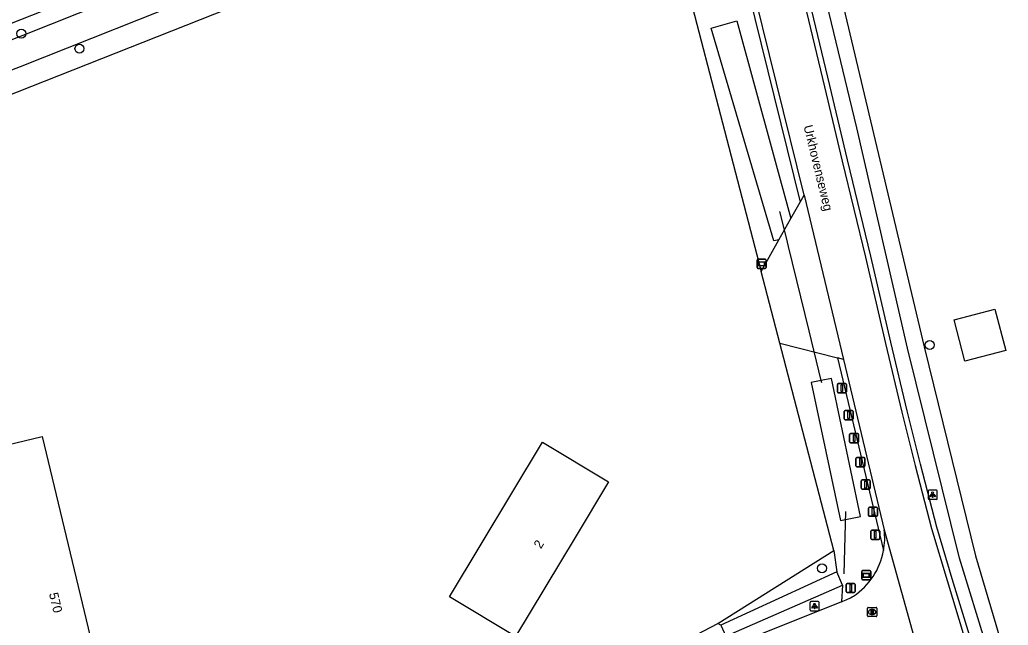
# Model space of a CAD drawing. Extents: x 164494 to 166241, y 382475 to 384494.
# Drawn here: x 164719.3 to 164827, y 383502.5 to 383568.4 of the extents above; entities that cross this region are included whole.
import ezdxf

# ---------------------------------------------------------------- set-up
doc = ezdxf.new("R2010")
doc.units = 0
for name, color, linetype in [('IMGEO_Afsluitpaal', 7, 'Continuous'), ('IMGEO_Berm_halfverhard', 7, 'Continuous'), ('IMGEO_Boom', 7, 'Continuous'), ('IMGEO_Duiker', 7, 'Continuous'), ('IMGEO_Fietspad_open', 7, 'Continuous'), ('IMGEO_Groenvoorziening', 7, 'Continuous'), ('IMGEO_Lichtpunt', 7, 'Continuous'), ('IMGEO_Openbare_ruimte_label', 7, 'Continuous'), ('IMGEO_Pand', 7, 'Continuous'), ('IMGEO_Pand_nummerreeks', 7, 'Continuous'), ('IMGEO_Rijbaan_lokaal_gesloten', 7, 'Continuous'), ('IMGEO_Rijbaan_lokaal_open', 7, 'Continuous'), ('IMGEO_Rioolput', 7, 'Continuous'), ('IMGEO_Straatnaambord', 7, 'Continuous'), ('IMGEO_Verklikker', 7, 'Continuous'), ('IMGEO_Voetpad_open', 7, 'Continuous'), ('IMGEO_Waterloop', 7, 'Continuous')]:
    doc.layers.add(name, color=color, linetype=linetype)

msp = doc.modelspace()

# ---------------------------------------------------------------- linework, layer by layer
at = {"layer": 'IMGEO_Afsluitpaal'}
for p, q in [((164808.38, 383527.91), (164808.38, 383528.71)), ((164808.38, 383528.71), (164808.38, 383527.91)), ((164808.48, 383528.81), (164809.27, 383528.81)), ((164809.27, 383528.81), (164808.48, 383528.81)), ((164809.37, 383528.71), (164809.37, 383527.91)), ((164809.37, 383527.91), (164809.37, 383528.71)), ((164809.27, 383527.81), (164808.48, 383527.81)), ((164808.48, 383527.81), (164809.27, 383527.81)), ((164809.22, 383525.88), (164810.01, 383525.88)), ((164810.01, 383525.88), (164809.22, 383525.88)), ((164809.12, 383524.98), (164809.12, 383525.78)), ((164809.12, 383525.78), (164809.12, 383524.98)), ((164810.01, 383524.88), (164809.22, 383524.88)), ((164809.22, 383524.88), (164810.01, 383524.88)), ((164810.11, 383525.78), (164810.11, 383524.98)), ((164810.11, 383524.98), (164810.11, 383525.78)), ((164809.71, 383522.47), (164809.71, 383523.27)), ((164809.71, 383523.27), (164809.71, 383522.47)), ((164809.81, 383523.37), (164810.6, 383523.37)), ((164810.6, 383523.37), (164809.81, 383523.37)), ((164810.7, 383523.27), (164810.7, 383522.47)), ((164810.7, 383522.47), (164810.7, 383523.27)), ((164810.6, 383522.37), (164809.81, 383522.37)), ((164809.81, 383522.37), (164810.6, 383522.37)), ((164810.4, 383519.86), (164810.4, 383520.66)), ((164810.4, 383520.66), (164810.4, 383519.86)), ((164810.5, 383520.76), (164811.29, 383520.76)), ((164811.29, 383520.76), (164810.5, 383520.76)), ((164811.39, 383520.66), (164811.39, 383519.86)), ((164811.39, 383519.86), (164811.39, 383520.66)), ((164811.29, 383519.76), (164810.5, 383519.76)), ((164810.5, 383519.76), (164811.29, 383519.76)), ((164810.97, 383517.42), (164810.97, 383518.22)), ((164810.97, 383518.22), (164810.97, 383517.42)), ((164811.07, 383518.32), (164811.86, 383518.32)), ((164811.86, 383518.32), (164811.07, 383518.32)), ((164811.86, 383517.32), (164811.07, 383517.32)), ((164811.07, 383517.32), (164811.86, 383517.32)), ((164811.96, 383518.22), (164811.96, 383517.42)), ((164811.96, 383517.42), (164811.96, 383518.22)), ((164811.77, 383514.46), (164811.77, 383515.26)), ((164811.77, 383515.26), (164811.77, 383514.46)), ((164811.87, 383515.36), (164812.66, 383515.36)), ((164812.66, 383515.36), (164811.87, 383515.36)), ((164812.76, 383515.26), (164812.76, 383514.46)), ((164812.76, 383514.46), (164812.76, 383515.26)), ((164812.66, 383514.36), (164811.87, 383514.36)), ((164811.87, 383514.36), (164812.66, 383514.36)), ((164812.02, 383511.95), (164812.02, 383512.75)), ((164812.02, 383512.75), (164812.02, 383511.95)), ((164812.12, 383512.85), (164812.91, 383512.85)), ((164812.91, 383512.85), (164812.12, 383512.85)), ((164813.01, 383512.75), (164813.01, 383511.95)), ((164813.01, 383511.95), (164813.01, 383512.75)), ((164812.91, 383511.85), (164812.12, 383511.85)), ((164812.12, 383511.85), (164812.91, 383511.85)), ((164809.34, 383506.16), (164809.34, 383506.95)), ((164809.34, 383506.95), (164809.34, 383506.16)), ((164809.44, 383507.05), (164810.23, 383507.05)), ((164810.23, 383507.05), (164809.44, 383507.05)), ((164810.33, 383506.95), (164810.33, 383506.16)), ((164810.33, 383506.16), (164810.33, 383506.95)), ((164810.23, 383506.06), (164809.44, 383506.06)), ((164809.44, 383506.06), (164810.23, 383506.06))]:
    msp.add_line(p, q, dxfattribs=at)
for points in [[(164808.8, 383528.69), (164808.95, 383528.69), (164808.95, 383527.94), (164808.8, 383527.94), (164808.8, 383528.69)], [(164809.54, 383525.76), (164809.69, 383525.76), (164809.69, 383525.01), (164809.54, 383525.01), (164809.54, 383525.76)], [(164810.13, 383523.25), (164810.28, 383523.25), (164810.28, 383522.5), (164810.13, 383522.5), (164810.13, 383523.25)], [(164810.82, 383520.64), (164810.97, 383520.64), (164810.97, 383519.89), (164810.82, 383519.89), (164810.82, 383520.64)], [(164811.39, 383518.19), (164811.54, 383518.19), (164811.54, 383517.44), (164811.39, 383517.44), (164811.39, 383518.19)], [(164812.19, 383515.24), (164812.34, 383515.24), (164812.34, 383514.49), (164812.19, 383514.49), (164812.19, 383515.24)], [(164812.44, 383512.73), (164812.59, 383512.73), (164812.59, 383511.98), (164812.44, 383511.98), (164812.44, 383512.73)], [(164809.76, 383506.93), (164809.91, 383506.93), (164809.91, 383506.18), (164809.76, 383506.18), (164809.76, 383506.93)]]:
    msp.add_lwpolyline(points, dxfattribs=at)
for centre, start, end in [((164808.48, 383528.71), 90, 180), ((164808.48, 383528.71), 90, 180), ((164809.27, 383528.71), 0, 90), ((164809.27, 383528.71), 360, 90), ((164808.48, 383527.91), 180, 270), ((164808.48, 383527.91), 180, 270), ((164809.27, 383527.91), 270, 0), ((164809.27, 383527.91), 270, 0), ((164809.22, 383525.78), 90, 180), ((164809.22, 383525.78), 90, 180), ((164810.01, 383525.78), 0, 90), ((164810.01, 383525.78), 360, 90), ((164809.22, 383524.98), 180, 270), ((164809.22, 383524.98), 180, 270), ((164810.01, 383524.98), 270, 0), ((164810.01, 383524.98), 270, 0), ((164809.81, 383523.27), 90, 180), ((164809.81, 383523.27), 90, 180), ((164810.6, 383523.27), 0, 90), ((164810.6, 383523.27), 360, 90), ((164809.81, 383522.47), 180, 270), ((164809.81, 383522.47), 180, 270), ((164810.6, 383522.47), 270, 0), ((164810.6, 383522.47), 270, 0), ((164810.5, 383520.66), 90, 180), ((164810.5, 383520.66), 90, 180), ((164811.29, 383520.66), 0, 90), ((164811.29, 383520.66), 360, 90), ((164810.5, 383519.86), 180, 270), ((164810.5, 383519.86), 180, 270), ((164811.29, 383519.86), 270, 0), ((164811.29, 383519.86), 270, 0), ((164811.07, 383518.22), 90, 180), ((164811.07, 383518.22), 90, 180), ((164811.07, 383517.42), 180, 270), ((164811.07, 383517.42), 180, 270), ((164811.86, 383518.22), 0, 90), ((164811.86, 383518.22), 360, 90), ((164811.86, 383517.42), 270, 0), ((164811.86, 383517.42), 270, 0), ((164811.87, 383515.26), 90, 180), ((164811.87, 383515.26), 90, 180), ((164812.66, 383515.26), 0, 90), ((164812.66, 383515.26), 360, 90), ((164811.87, 383514.46), 180, 270), ((164811.87, 383514.46), 180, 270), ((164812.66, 383514.46), 270, 0), ((164812.66, 383514.46), 270, 0), ((164812.12, 383512.75), 90, 180), ((164812.12, 383512.75), 90, 180), ((164812.12, 383511.95), 180, 270), ((164812.12, 383511.95), 180, 270), ((164812.91, 383512.75), 0, 90), ((164812.91, 383512.75), 360, 90), ((164812.91, 383511.95), 270, 0), ((164812.91, 383511.95), 270, 0), ((164809.44, 383506.95), 90, 180), ((164809.44, 383506.95), 90, 180), ((164810.23, 383506.95), 0, 90), ((164810.23, 383506.95), 360, 90), ((164809.44, 383506.16), 180, 270), ((164809.44, 383506.16), 180, 270), ((164810.23, 383506.16), 270, 0), ((164810.23, 383506.16), 270, 0)]:
    msp.add_arc(centre, 0.1, start, end, dxfattribs=at)
at = {"layer": 'IMGEO_Berm_halfverhard'}
for points in [[(164824.21, 383497.04), (164822.78, 383501.42), (164820.9, 383507.55), (164819.23, 383513.17), (164817.43, 383520.04), (164815.99, 383525.83), (164814.22, 383533.33), (164812.04, 383542.71), (164809.5, 383553.19), (164807.57, 383561.29), (164803.45, 383578.4), (164801.35, 383586.99), (164800.92, 383586.88)], [(164795.71, 383585.96), (164795.13, 383585.81), (164804.32, 383548.59)], [(164808.4, 383531.62), (164813.41, 383510.63)]]:
    msp.add_lwpolyline(points, dxfattribs=at)
at = {"layer": 'IMGEO_Boom'}
for centre in [(164719.49, 383566.93), (164725.83, 383565.3), (164818.45, 383533.02), (164806.71, 383508.7)]:
    msp.add_circle(centre, 0.489, dxfattribs=at)
at = {"layer": 'IMGEO_Duiker'}
for points in [[(164806.69, 383528.89), (164806.63, 383529.16), (164805.3, 383534.57), (164803.06, 383543.73), (164802.83, 383544.68), (164802.13, 383547.55)], [(164809.12, 383508.11), (164809.32, 383514.9)]]:
    msp.add_lwpolyline(points, dxfattribs=at)
at = {"layer": 'IMGEO_Fietspad_open'}
for points in [[(164780.31, 383592.48), (164780.67, 383591.01), (164719.66, 383566.74), (164702.48, 383560.05), (164631.23, 383531.62)], [(164543.61, 383493.49), (164560.1, 383500), (164646.9, 383534.43), (164687.9, 383550.87), (164703.45, 383557.25), (164719.42, 383563.36), (164781.38, 383588), (164789.86, 383591.37)]]:
    msp.add_lwpolyline(points, dxfattribs=at)
at = {"layer": 'IMGEO_Groenvoorziening'}
for points in [[(164787.93, 383587.83), (164800.09, 383541.03)], [(164807.99, 383510.62), (164802.12, 383533.21)], [(164795.36, 383502.7), (164807.99, 383510.62)], [(164807.99, 383510.62), (164808.34, 383508.3)], [(164808.96, 383506.85), (164808.83, 383505.04)], [(164757.54, 383480.47), (164762.71, 383483.34), (164781.14, 383494.37), (164788.51, 383499.08), (164795.36, 383502.7)], [(164795.7, 383502.5), (164795.36, 383502.7)]]:
    msp.add_lwpolyline(points, dxfattribs=at)
at = {"layer": 'IMGEO_Lichtpunt'}
for p, q in [((164818.26, 383517.11), (164818.26, 383516.3)), ((164818.26, 383517.11), (164818.26, 383516.3)), ((164819.17, 383517.2), (164818.36, 383517.2)), ((164819.17, 383517.2), (164818.36, 383517.2)), ((164818.36, 383516.21), (164819.17, 383516.21)), ((164818.36, 383516.21), (164819.17, 383516.21)), ((164819.26, 383516.3), (164819.26, 383517.11)), ((164819.26, 383516.3), (164819.26, 383517.11)), ((164805.4, 383504.98), (164805.4, 383504.18)), ((164805.4, 383504.98), (164805.4, 383504.18)), ((164806.3, 383505.08), (164805.5, 383505.08)), ((164806.3, 383505.08), (164805.5, 383505.08)), ((164806.4, 383504.18), (164806.4, 383504.98)), ((164806.4, 383504.18), (164806.4, 383504.98)), ((164805.5, 383504.08), (164806.3, 383504.08)), ((164805.5, 383504.08), (164806.3, 383504.08))]:
    msp.add_line(p, q, dxfattribs=at)
for points in [[(164818.64, 383516.77), (164818.68, 383516.74), (164818.49, 383516.48), (164818.45, 383516.51), (164818.64, 383516.77)], [(164818.74, 383516.72), (164818.79, 383516.72), (164818.79, 383516.4), (164818.74, 383516.4), (164818.74, 383516.72)], [(164818.85, 383516.74), (164818.89, 383516.77), (164819.08, 383516.51), (164819.04, 383516.48), (164818.85, 383516.74)], [(164805.78, 383504.65), (164805.81, 383504.62), (164805.63, 383504.36), (164805.59, 383504.38), (164805.78, 383504.65)], [(164805.88, 383504.6), (164805.92, 383504.6), (164805.92, 383504.28), (164805.88, 383504.28), (164805.88, 383504.6)], [(164805.99, 383504.62), (164806.03, 383504.65), (164806.21, 383504.38), (164806.17, 383504.36), (164805.99, 383504.62)]]:
    msp.add_lwpolyline(points, dxfattribs=at)
for centre in [(164818.76, 383516.91), (164805.9, 383504.78)]:
    msp.add_circle(centre, 0.0994, dxfattribs=at)
for centre, start, end in [((164818.36, 383517.11), 90, 180), ((164818.36, 383517.11), 90, 180), ((164818.36, 383516.3), 180, 270), ((164818.36, 383516.3), 180, 270), ((164819.17, 383517.11), 0, 90), ((164819.17, 383517.11), 0, 90), ((164819.17, 383516.3), 270, 0), ((164819.17, 383516.3), 270, 360), ((164805.5, 383504.98), 90, 180), ((164805.5, 383504.98), 90, 180), ((164806.3, 383504.98), 0, 90), ((164806.3, 383504.98), 0, 90), ((164805.5, 383504.18), 180, 270), ((164805.5, 383504.18), 180, 270), ((164806.3, 383504.18), 270, 0), ((164806.3, 383504.18), 270, 360)]:
    msp.add_arc(centre, 0.0946, start, end, dxfattribs=at)
at = {"layer": 'IMGEO_Pand'}
for points in [[(164826.72, 383532.41), (164822.26, 383531.25), (164821.1, 383535.75), (164825.55, 383536.91), (164826.72, 383532.41)], [(164730.27, 383487.65), (164656.03, 383469.75), (164647.47, 383505.18), (164721.76, 383523.07), (164730.27, 383487.65)], [(164776.26, 383522.42), (164783.45, 383518.11), (164779.82, 383512.07), (164773.34, 383501.28), (164766.15, 383505.6), (164776.26, 383522.42)]]:
    msp.add_lwpolyline(points, dxfattribs=at)
at = {"layer": 'IMGEO_Rijbaan_lokaal_gesloten'}
for points in [[(164800.92, 383586.88), (164800.77, 383586.85), (164802.87, 383578.26), (164806.99, 383561.15), (164808.92, 383553.05), (164811.46, 383542.57), (164813.64, 383533.19), (164815.41, 383525.69), (164816.85, 383519.9), (164818.65, 383513.02), (164820.33, 383507.38), (164822.21, 383501.24), (164823.6, 383496.99), (164823.73, 383497)], [(164804.75, 383549.35), (164795.71, 383585.96)], [(164804.75, 383549.35), (164809.06, 383531.45)], [(164809.06, 383531.45), (164813.49, 383512.88)], [(164813.49, 383512.88), (164817.27, 383499.31)]]:
    msp.add_lwpolyline(points, dxfattribs=at)
at = {"layer": 'IMGEO_Rijbaan_lokaal_open'}
for points in [[(164631.55, 383533.52), (164682.65, 383553.76), (164703.01, 383561.99), (164780.31, 383592.48)], [(164808.83, 383505.04), (164796.22, 383500), (164794.75, 383499.41), (164790.47, 383497.07), (164770.36, 383485.2), (164745.59, 383470.14), (164736.07, 383464.54)]]:
    msp.add_lwpolyline(points, dxfattribs=at)
for centre, radius, start, end in [((164805.75, 383512.03), 7.79, 349.6448, 6.2225), ((164805.89, 383512.03), 7.65, 303.7934, 349.4738), ((164805.02, 383514.61), 10.3, 291.6906, 299.8261)]:
    msp.add_arc(centre, radius, start, end, dxfattribs=at)
at = {"layer": 'IMGEO_Rioolput'}
for p, q in [((164811.67, 383503.51), (164811.67, 383504.36)), ((164811.75, 383504.44), (164812.6, 383504.44)), ((164812.67, 383504.36), (164812.67, 383503.51)), ((164812.6, 383503.43), (164811.75, 383503.43)), ((164812.16, 383504.21), (164812.19, 383504.21)), ((164812.18, 383503.66), (164812.16, 383503.66))]:
    msp.add_line(p, q, dxfattribs=at)
for points in [[(164811.67, 383503.51), (164811.67, 383504.36)], [(164811.75, 383504.44), (164812.6, 383504.44)], [(164812.67, 383504.36), (164812.67, 383503.51)], [(164812.6, 383503.43), (164811.75, 383503.43)], [(164812.26, 383504.13), (164812.01, 383504.13), (164812.01, 383503.73)], [(164812.01, 383503.73), (164812.13, 383503.73), (164812.13, 383503.9), (164812.15, 383503.9)], [(164812.19, 383504.05), (164812.13, 383504.05), (164812.13, 383503.97)], [(164812.13, 383503.97), (164812.19, 383503.97)], [(164812.19, 383503.87), (164812.26, 383503.73), (164812.4, 383503.73), (164812.34, 383503.86)]]:
    msp.add_lwpolyline(points, dxfattribs=at)
for centre, radius, start, end in [((164811.75, 383504.36), 0.0765, 91.552, 178.448), ((164811.75, 383504.36), 0.0765, 91.552, 178.448), ((164812.6, 383504.36), 0.0765, 1.552, 88.448), ((164812.6, 383504.36), 0.0765, 1.552, 88.448), ((164811.75, 383503.51), 0.0765, 181.552, 268.448), ((164811.75, 383503.51), 0.0765, 181.552, 268.448), ((164812.14, 383503.84), 0.0533, 26.0293, 88.6989), ((164812.19, 383503.96), 0.0964, 77.0061, 93.1865), ((164812.17, 383504.16), 0.19, 274.7715, 282.9687), ((164812.21, 383504.01), 0.0378, 276.6634, 79.6772), ((164812.26, 383504.02), 0.109, 350.3612, 89.416), ((164812.26, 383504.02), 0.112, 277.5842, 350.9817), ((164812.24, 383503.81), 0.108, 29.5134, 73.7905), ((164812.6, 383503.51), 0.0765, 271.552, 358.448), ((164812.6, 383503.51), 0.0765, 271.552, 358.448)]:
    msp.add_arc(centre, radius, start, end, dxfattribs=at)
for centre, major_axis, ratio, start_param, end_param in [((164812.16, 383503.93), (-0.387, 0.002), 0.722429, 4.712389, 7.853982), ((164812.18, 383503.93), (-0.39, 0.002), 0.717154, 1.570796, 4.712389)]:
    msp.add_ellipse(centre, major_axis=major_axis, ratio=ratio, start_param=start_param, end_param=end_param, dxfattribs=at)
at = {"layer": 'IMGEO_Straatnaambord'}
for p, q in [((164811.03, 383507.54), (164811.03, 383508.34)), ((164811.03, 383508.34), (164811.03, 383507.54)), ((164811.13, 383508.44), (164811.92, 383508.44)), ((164811.92, 383508.44), (164811.13, 383508.44)), ((164812.02, 383508.34), (164812.02, 383507.54)), ((164812.02, 383507.54), (164812.02, 383508.34)), ((164811.92, 383507.44), (164811.13, 383507.44)), ((164811.13, 383507.44), (164811.92, 383507.44))]:
    msp.add_line(p, q, dxfattribs=at)
for points in [[(164811.13, 383508.17), (164811.92, 383508.17), (164811.92, 383507.71), (164811.13, 383507.71), (164811.13, 383508.17)], [(164811.2, 383508.11), (164811.2, 383507.77), (164811.86, 383507.77), (164811.86, 383508.11), (164811.2, 383508.11)]]:
    msp.add_lwpolyline(points, dxfattribs=at)
for centre, start, end in [((164811.13, 383508.34), 90, 180), ((164811.13, 383508.34), 90, 180), ((164811.92, 383508.34), 0, 90), ((164811.92, 383508.34), 360, 90), ((164811.13, 383507.54), 180, 270), ((164811.13, 383507.54), 180, 270), ((164811.92, 383507.54), 270, 0), ((164811.92, 383507.54), 270, 0)]:
    msp.add_arc(centre, 0.1, start, end, dxfattribs=at)
at = {"layer": 'IMGEO_Verklikker'}
for p, q in [((164799.63, 383541.46), (164799.63, 383542.26)), ((164799.63, 383542.26), (164799.63, 383541.46)), ((164799.73, 383542.36), (164800.52, 383542.36)), ((164800.52, 383542.36), (164799.73, 383542.36)), ((164800.62, 383542.26), (164800.62, 383541.46)), ((164800.62, 383541.46), (164800.62, 383542.26)), ((164800.52, 383541.36), (164799.73, 383541.36)), ((164799.73, 383541.36), (164800.52, 383541.36))]:
    msp.add_line(p, q, dxfattribs=at)
for points in [[(164799.73, 383542.09), (164800.52, 383542.09), (164800.52, 383541.63), (164799.73, 383541.63), (164799.73, 383542.09)], [(164799.8, 383542.03), (164799.8, 383541.69), (164800.45, 383541.69), (164800.45, 383542.03), (164799.8, 383542.03)]]:
    msp.add_lwpolyline(points, dxfattribs=at)
for centre, start, end in [((164799.73, 383542.26), 90, 180), ((164799.73, 383542.26), 90, 180), ((164800.52, 383542.26), 0, 90), ((164800.52, 383542.26), 360, 90), ((164799.73, 383541.46), 180, 270), ((164799.73, 383541.46), 180, 270), ((164800.52, 383541.46), 270, 0), ((164800.52, 383541.46), 270, 0)]:
    msp.add_arc(centre, 0.1, start, end, dxfattribs=at)
at = {"layer": 'IMGEO_Voetpad_open'}
for points in [[(164787.93, 383587.83), (164781.97, 383585.47), (164705.12, 383555.08), (164637.45, 383528.24), (164634.35, 383527)], [(164803.33, 383546.81), (164804.32, 383548.59)], [(164804.32, 383548.59), (164804.75, 383549.35)], [(164802.02, 383544.48), (164803.33, 383546.81)], [(164800.09, 383541.03), (164802.02, 383544.48)], [(164802.12, 383533.21), (164800.09, 383541.03)], [(164802.12, 383533.21), (164808.4, 383531.62)], [(164809.06, 383531.45), (164808.4, 383531.62)]]:
    msp.add_lwpolyline(points, dxfattribs=at)
at = {"layer": 'IMGEO_Waterloop'}
for points in [[(164826.99, 383498.07), (164825.46, 383497.55), (164824.71, 383500), (164821.68, 383509.81), (164816.04, 383532.67), (164810.51, 383556.66), (164807.22, 383570.21), (164806.67, 383572.09), (164806.33, 383573.27)], [(164808.73, 383571.24), (164817.84, 383532.83), (164823.42, 383510.07), (164826.42, 383500), (164826.99, 383498.07)], [(164802.02, 383544.48), (164801.48, 383544.35), (164794.62, 383567.54), (164797.42, 383568.33), (164803.33, 383546.81)], [(164808.73, 383513.91), (164810.92, 383514.33), (164807.75, 383529.37), (164806.63, 383529.16), (164805.52, 383528.95), (164808.73, 383513.91)], [(164808.34, 383508.3), (164795.7, 383502.5)], [(164808.96, 383506.85), (164808.34, 383508.3)], [(164795.7, 383502.5), (164796.24, 383501.3), (164808.96, 383506.85)]]:
    msp.add_lwpolyline(points, dxfattribs=at)

# ---------------------------------------------------------------- texts
at = {"layer": 'IMGEO_Openbare_ruimte_label'}
msp.add_text('Urkhovenseweg', height=1, rotation=283.6472, dxfattribs=at).set_placement((164804.69, 383556.85))
at = {"layer": 'IMGEO_Pand_nummerreeks'}
for s, rotation, p in [('2', 58.9937, (164776.09, 383510.75)), ('570', 283.5083, (164722.5, 383505.93))]:
    msp.add_text(s, height=1, rotation=rotation, dxfattribs=at).set_placement(p)

doc.saveas('drawing.dxf')
